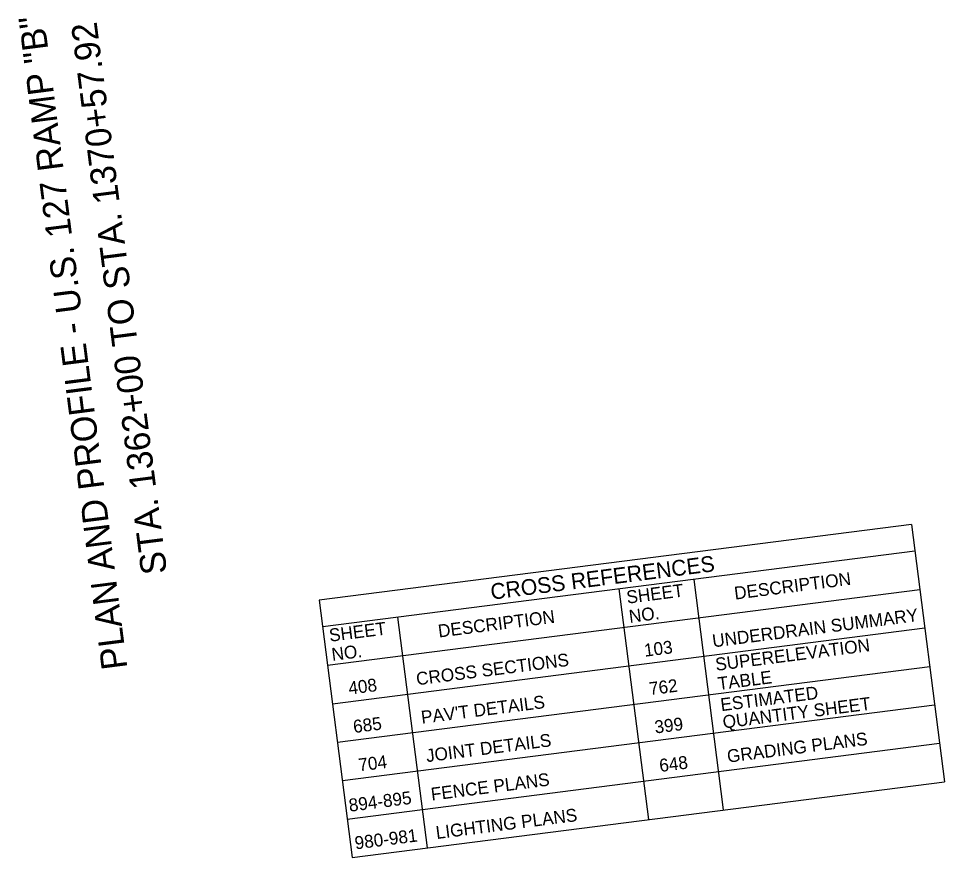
# Model space of a CAD drawing. Extents: x -64485748 to 1397784, y -34873821 to 573585.
# Drawn here: x 1397333.9 to 1397784, y 572043.1 to 572450.9 of the extents above; entities that cross this region are included whole.
import ezdxf

# ---------------------------------------------------------------- set-up
doc = ezdxf.new("R2010")
doc.units = 0
doc.layers.add('Level 1', color=7, linetype='Continuous')
doc.layers.add('Level 40', color=7, linetype='Continuous')

msp = doc.modelspace()

# ---------------------------------------------------------------- linework, layer by layer
at = {"layer": 'Level 40'}
for p, q in [((1397768.02, 572204.95), (1397480.09, 572168.11)), ((1397768.02, 572204.95), (1397784.02, 572079.95)), ((1397769.67, 572192.04), (1397481.74, 572155.2)), ((1397662.12, 572178.28), (1397676.47, 572066.19)), ((1397484.13, 572136.52), (1397772.06, 572173.36)), ((1397625.71, 572173.62), (1397640.05, 572061.53)), ((1397480.09, 572168.11), (1397496.08, 572043.11)), ((1397518.16, 572159.86), (1397532.5, 572047.77)), ((1397486.52, 572117.84), (1397774.45, 572154.68)), ((1397488.91, 572099.16), (1397776.85, 572136)), ((1397491.3, 572080.48), (1397779.24, 572117.32)), ((1397493.69, 572061.79), (1397781.63, 572098.64)), ((1397496.08, 572043.11), (1397784.02, 572079.95))]:
    msp.add_line(p, q, dxfattribs=at)

# ---------------------------------------------------------------- texts
at = {"layer": 'Level 1'}
for s, p in [('PLAN AND PROFILE - U.S. 127 RAMP "B"', (1397386.83, 572135.18)), ('STA. 1362+00 TO STA. 1370+57.92', (1397406.11, 572181.46))]:
    msp.add_text(s, height=12.5, rotation=97.2913, dxfattribs=at).set_placement(p)
at = {"layer": 'Level 40'}
for s, height, p in [('CROSS REFERENCES', 7.6923, (1397563.82, 572168.38)), ('DESCRIPTION', 6.25, (1397682.21, 572168.42)), ('SHEET ', 6.25, (1397629.83, 572166.45)), ('NO.', 6.25, (1397631.02, 572157.15)), ('DESCRIPTION', 6.25, (1397538.24, 572150)), ('UNDERDRAIN SUMMARY', 6.25, (1397671.55, 572145.21)), ('SHEET ', 6.25, (1397485.27, 572147.95)), (' 103', 6.25, (1397636.06, 572140.37)), ('SUPERELEVATION  ', 6.25, (1397673.01, 572133.8)), ('NO.', 6.25, (1397486.46, 572138.65)), ('CROSS SECTIONS  ', 6.25, (1397527.59, 572126.78)), ('TABLE           ', 6.25, (1397674.21, 572124.46)), (' 408', 6.25, (1397492.34, 572121.98)), (' 762', 6.25, (1397638.5, 572121.69)), ('ESTIMATED       ', 6.25, (1397675.52, 572114.2)), ("PAV'T DETAILS   ", 6.25, (1397529.98, 572108.1)), ('QUANTITY SHEET  ', 6.25, (1397676.6, 572105.78)), (' 685', 6.25, (1397494.63, 572103.28)), (' 399', 6.25, (1397641.16, 572103.04)), ('JOINT DETAILS   ', 6.25, (1397532.37, 572089.42)), ('GRADING PLANS   ', 6.25, (1397678.72, 572089.16)), (' 704', 6.25, (1397497.19, 572084.62)), (' 648', 6.25, (1397643.48, 572084.35)), ('FENCE PLANS     ', 6.25, (1397534.76, 572070.74)), ('894-895', 6.25, (1397494.83, 572065.33)), ('LIGHTING PLANS', 6.25, (1397537.15, 572052.06)), ('980-981  ', 6.25, (1397497.7, 572047.02))]:
    msp.add_text(s, height=height, rotation=7.2913, dxfattribs=at).set_placement(p)

doc.saveas('drawing.dxf')
